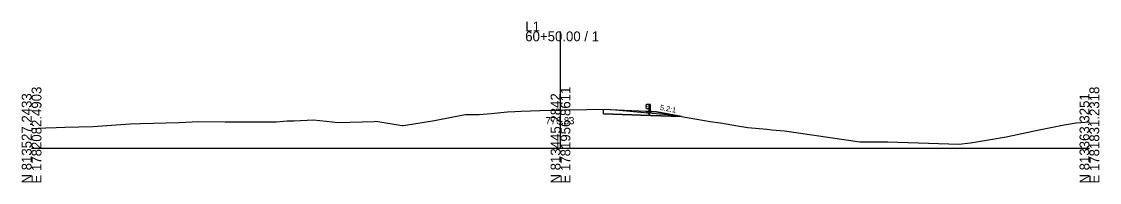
# Model space of a CAD drawing. Extents: x 5574 to 10203, y -10 to 9546.
# Drawn here: x 6597.2 to 6902.8, y 7990.3 to 8035.9 of the extents above; entities that cross this region are included whole.
import ezdxf

# ---------------------------------------------------------------- set-up
doc = ezdxf.new("R2010")
doc.units = 0
for name, color, linetype in [('Exist Cross Section Cell', 7, 'Continuous'), ('Exist XS Center Line Elevation Label', 7, 'Continuous'), ('Exist XS Ground Line', 7, 'Continuous'), ('Prop XS Ditch Slope Text', 7, 'Continuous'), ('Prop XS Earthwork Shape', 7, 'Continuous'), ('Prop XS Finish Grade', 7, 'Continuous'), ('Prop XS Finish Grade Pavement', 7, 'Continuous'), ('Prop XS Guardrail', 7, 'Continuous'), ('Prop XS Pvmt Edge Slope', 7, 'Continuous'), ('Prop XS Subgrade Earthwork', 7, 'Continuous'), ('Scratch_Level_3', 7, 'Continuous'), ('Scratch_Level_6', 7, 'Continuous')]:
    doc.layers.add(name, color=color, linetype=linetype)

msp = doc.modelspace()

# ---------------------------------------------------------------- linework, layer by layer
at = {"layer": 'Exist Cross Section Cell'}
for p, q in [((6750, 8000), (6750, 8033.15)), ((6600, 8000), (6750, 8000)), ((6750, 8000), (6900, 8000))]:
    msp.add_line(p, q, dxfattribs=at)
at = {"layer": 'Exist XS Ground Line'}
for p, q in [((6714.24, 8007.89), (6719.52, 8008.88)), ((6719.52, 8008.88), (6723.09, 8009.54)), ((6723.09, 8009.54), (6726.96, 8009.6)), ((6726.96, 8009.6), (6730.33, 8009.82)), ((6730.33, 8009.82), (6735, 8010.32)), ((6735, 8010.32), (6737.05, 8010.42)), ((6737.05, 8010.42), (6738.82, 8010.52)), ((6738.82, 8010.52), (6744.13, 8010.67)), ((6744.13, 8010.67), (6750, 8010.83)), ((6750, 8010.83), (6751.09, 8010.86)), ((6751.09, 8010.86), (6757.49, 8010.96)), ((6757.49, 8010.96), (6762.2, 8011.05)), ((6762.2, 8011.05), (6764.09, 8010.96)), ((6764.09, 8010.96), (6765.6, 8010.89)), ((6765.6, 8010.89), (6774.87, 8010.06)), ((6774.87, 8010.06), (6780.48, 8009.54)), ((6780.48, 8009.54), (6784.31, 8008.97)), ((6784.31, 8008.97), (6792.47, 8007.61)), ((6604.01, 8005.76), (6607, 8005.91)), ((6607, 8005.91), (6609.44, 8005.97)), ((6609.44, 8005.97), (6617.36, 8006.22)), ((6617.36, 8006.22), (6627.95, 8006.91)), ((6627.95, 8006.91), (6630.89, 8007.06)), ((6630.89, 8007.06), (6641.81, 8007.3)), ((6641.81, 8007.3), (6647.35, 8007.58)), ((6647.35, 8007.58), (6654.92, 8007.53)), ((6654.92, 8007.53), (6657.52, 8007.5)), ((6657.52, 8007.5), (6669.43, 8007.52)), ((6669.43, 8007.52), (6672.53, 8007.74)), ((6672.53, 8007.74), (6674.46, 8007.78)), ((6674.46, 8007.78), (6679.92, 8008.06)), ((6679.92, 8008.06), (6685.37, 8007.52)), ((6685.37, 8007.52), (6686.78, 8007.34)), ((6686.78, 8007.34), (6697.21, 8007.63)), ((6697.21, 8007.63), (6697.65, 8007.66)), ((6697.65, 8007.66), (6705.1, 8006.48)), ((6705.1, 8006.48), (6705.42, 8006.43)), ((6705.42, 8006.43), (6706.02, 8006.53)), ((6706.02, 8006.53), (6714.24, 8007.89)), ((6792.47, 8007.61), (6795.34, 8007.25)), ((6795.34, 8007.25), (6800.16, 8006.39)), ((6800.16, 8006.39), (6803.12, 8005.86)), ((6803.12, 8005.86), (6808.53, 8005.42)), ((6884.81, 8005.05), (6892.87, 8006.65)), ((6892.87, 8006.65), (6896.28, 8007.23)), ((6896.28, 8007.23), (6900, 8007.51)), ((6600, 8005.57), (6604.01, 8005.76)), ((6808.53, 8005.42), (6809.9, 8005.26)), ((6809.9, 8005.26), (6813.48, 8004.92)), ((6813.48, 8004.92), (6834.88, 8001.83)), ((6872.51, 8002.6), (6876.35, 8003.21)), ((6876.35, 8003.21), (6882.6, 8004.61)), ((6882.6, 8004.61), (6884.81, 8005.05)), ((6834.88, 8001.83), (6842.83, 8001.82)), ((6842.83, 8001.82), (6863.01, 8001.14)), ((6863.01, 8001.14), (6866.25, 8001.53)), ((6866.25, 8001.53), (6872.51, 8002.6))]:
    msp.add_line(p, q, dxfattribs=at)
at = {"layer": 'Prop XS Earthwork Shape'}
msp.add_lwpolyline([(6765.6, 8010.89), (6774.87, 8010.06), (6780.48, 8009.54), (6784.31, 8008.97), (6775.5, 8009.27), (6762.2, 8009.8), (6762.2, 8011.05), (6764.09, 8010.96)], close=True, dxfattribs=at)
at = {"layer": 'Prop XS Finish Grade'}
for p, q in [((6774.2, 8010.57), (6777.2, 8010.33)), ((6777.2, 8010.33), (6784.31, 8008.97))]:
    msp.add_line(p, q, dxfattribs=at)
at = {"layer": 'Prop XS Finish Grade Pavement'}
msp.add_line((6762.2, 8011.05), (6774.2, 8010.57), dxfattribs=at)
at = {"layer": 'Prop XS Guardrail'}
for p, q in [((6774.23, 8012.24), (6774.2, 8012.18)), ((6774.2, 8012.18), (6774.23, 8012.12)), ((6774.52, 8012.44), (6774.23, 8012.24)), ((6774.23, 8012.12), (6774.52, 8011.92)), ((6775.02, 8012.44), (6774.52, 8012.44)), ((6774.52, 8011.92), (6774.52, 8011.83)), ((6775.52, 8012.44), (6775.02, 8012.44)), ((6775.02, 8012.44), (6775.02, 8009.94)), ((6775.52, 8009.94), (6775.52, 8012.44)), ((6774.23, 8011.63), (6774.2, 8011.57)), ((6774.2, 8011.57), (6774.23, 8011.51)), ((6774.52, 8011.83), (6774.23, 8011.63)), ((6774.23, 8011.51), (6774.52, 8011.31)), ((6774.52, 8011.31), (6775.02, 8011.31))]:
    msp.add_line(p, q, dxfattribs=at)
at = {"layer": 'Prop XS Pvmt Edge Slope'}
msp.add_line((6774.2, 8010.57), (6775.5, 8009.27), dxfattribs=at)
at = {"layer": 'Prop XS Subgrade Earthwork'}
for p, q in [((6762.2, 8009.8), (6762.2, 8011.05)), ((6762.2, 8009.8), (6775.5, 8009.27)), ((6775.5, 8009.27), (6784.31, 8008.97))]:
    msp.add_line(p, q, dxfattribs=at)
at = {"layer": 'Scratch_Level_3'}
for p, q in [((6777.2, 8010.33), (6774.2, 8010.57)), ((6774.2, 8010.57), (6775.5, 8009.27)), ((6775.5, 8009.27), (6784.31, 8008.97)), ((6784.31, 8008.97), (6777.2, 8010.33))]:
    msp.add_line(p, q, dxfattribs=at)
at = {"layer": 'Scratch_Level_6'}
msp.add_lwpolyline([(6764.09, 8010.96), (6765.6, 8010.89), (6774.87, 8010.06), (6780.48, 8009.54), (6784.31, 8008.97), (6775.5, 8009.27), (6762.2, 8009.8), (6762.2, 8011.05)], close=True, dxfattribs=at)

# ---------------------------------------------------------------- texts
at = {"layer": 'Exist Cross Section Cell'}
for s, p in [('L1', (6740, 8033.15)), ('60+50.00 / 1', (6740, 8030.35))]:
    msp.add_text(s, height=2.8, dxfattribs=at).set_placement(p)
for s, p in [('N 813527.2433', (6600, 7990)), ('E 1782082.4903', (6602.8, 7990)), ('N 813445.2842', (6750, 7990)), ('E 1781956.8611', (6752.8, 7990)), ('N 813363.3251', (6900, 7990)), ('E 1781831.2318', (6902.8, 7990))]:
    msp.add_text(s, height=2.8, rotation=90, dxfattribs=at).set_placement(p)
at = {"layer": 'Exist XS Center Line Elevation Label'}
msp.add_text('776.83', height=2, dxfattribs=at).set_placement((6745.75, 8006.83))
at = {"layer": 'Prop XS Ditch Slope Text'}
msp.add_text('5.2:1', height=1.5, rotation=349.1835, dxfattribs=at).set_placement((6778.12, 8010.92))

doc.saveas('drawing.dxf')
